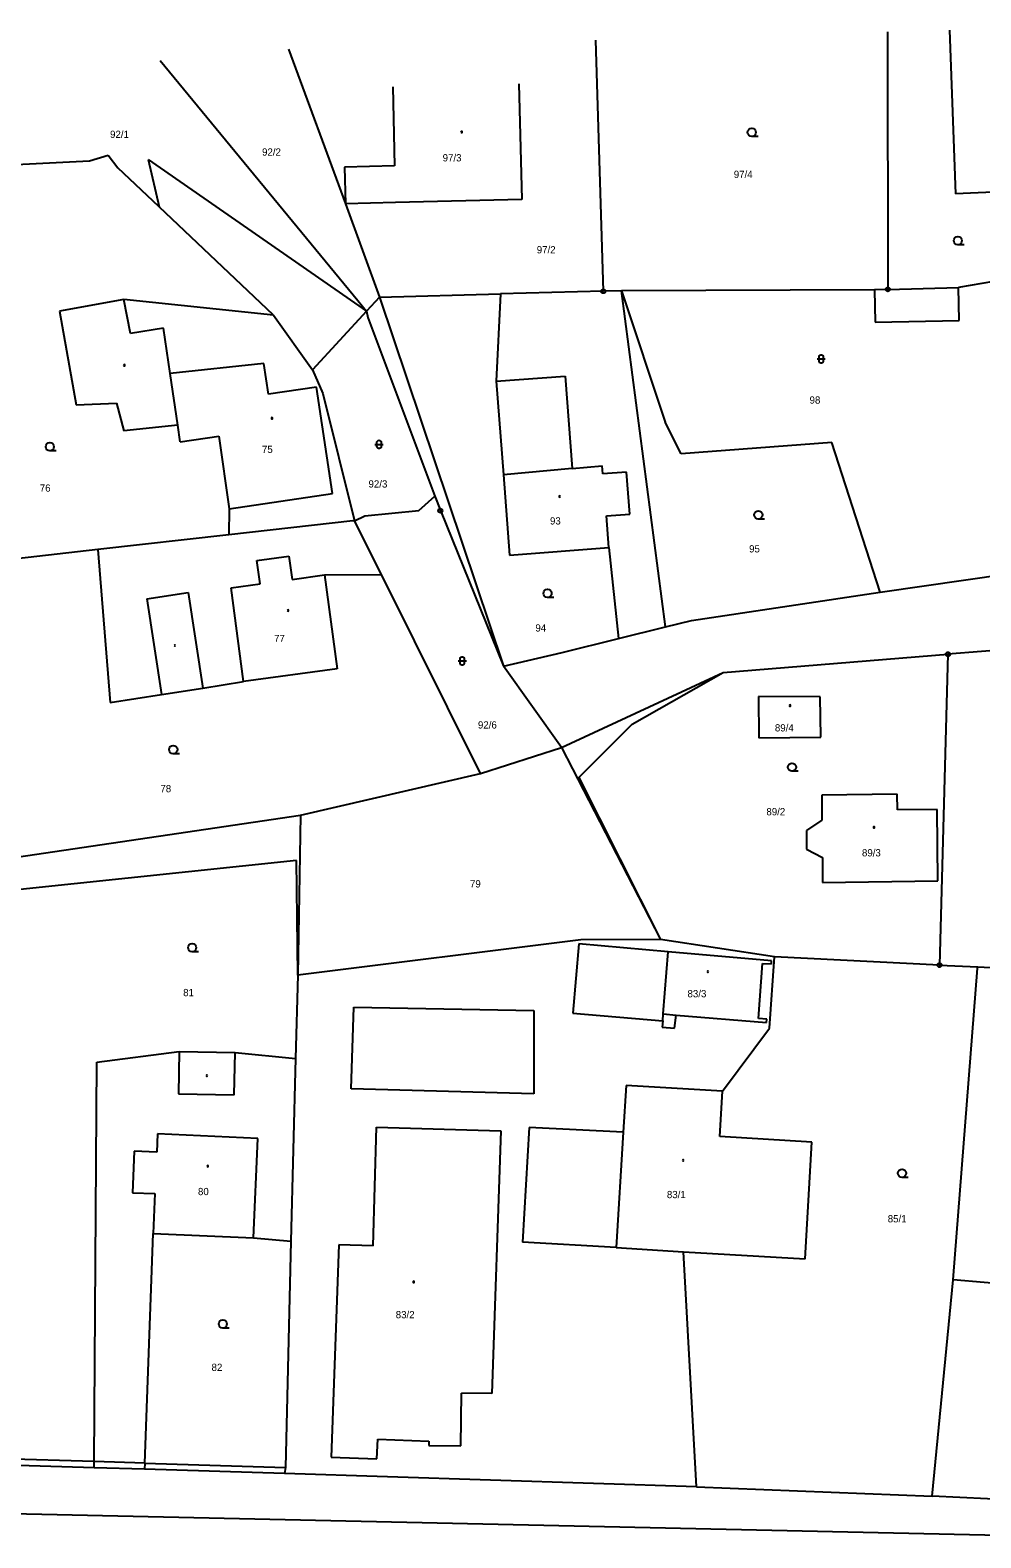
# Model space of a CAD drawing. Extents: x -454285 to -453563, y -1108687 to -1108249.
# Drawn here: x -453773.6 to -453681.8, y -1108476.1 to -1108330.4 of the extents above; entities that cross this region are included whole.
import ezdxf

# ---------------------------------------------------------------- set-up
doc = ezdxf.new("R2010")
doc.units = 0
for name, color, linetype in [('1', 7, 'Continuous'), ('14', 7, 'Continuous'), ('15', 7, 'Continuous'), ('2', 7, 'Continuous'), ('23', 7, 'Continuous'), ('25', 7, 'Continuous'), ('28', 7, 'Continuous')]:
    doc.layers.add(name, color=color, linetype=linetype)

# ---------------------------------------------------------------- blocks, each defined once
blk = doc.blocks.new('Z402')
for start, end in [(0, 180), (180, 0)]:
    blk.add_arc((0, 0), 0.15, start, end)
blk = doc.blocks.new('Z105')
for radius in [0.5, 0.01]:
    blk.add_circle((0, 0), radius)
blk = doc.blocks.new('Z3040')
blk.add_line((1.5, 0), (0, 0))
blk.add_circle((0, 1), 1)
blk = doc.blocks.new('Z3160')
for p, q in [((-1, 1), (1, 1)), ((-0.5, 1.6), (-0.4, 1.8)), ((-0.5, 0.4), (-0.5, 1.6)), ((-0.4, 0.2), (-0.5, 0.4)), ((-0.4, 1.8), (-0.3, 1.9)), ((-0.3, 0.1), (-0.4, 0.2)), ((-0.3, 1.9), (-0.1, 2)), ((-0.1, 0), (-0.3, 0.1)), ((-0.1, 2), (0.1, 2)), ((0.1, 0), (-0.1, 0)), ((0.1, 2), (0.3, 1.9)), ((0.3, 0.1), (0.1, 0)), ((0.3, 1.9), (0.4, 1.8)), ((0.4, 0.2), (0.3, 0.1)), ((0.4, 1.8), (0.5, 1.6)), ((0.5, 0.4), (0.4, 0.2)), ((0.5, 1.6), (0.5, 0.4))]:
    blk.add_line(p, q)

msp = doc.modelspace()

# ---------------------------------------------------------------- linework, layer by layer
at = {"layer": '1'}
for p, q in [((-453719.06, -1108331.41), (-453718.3, -1108355.65)), ((-453690.84, -1108330.6), (-453690.81, -1108355.47)), ((-453684.85, -1108330.43), (-453684.29, -1108346.25)), ((-453748.69, -1108332.26), (-453743.2, -1108347.21)), ((-453761.1, -1108333.35), (-453741.99, -1108356.55)), ((-453738.63, -1108335.9), (-453738.45, -1108343.53)), ((-453726.44, -1108335.6), (-453726.16, -1108346.79)), ((-453784.67, -1108343.91), (-453767.91, -1108343.04)), ((-453767.91, -1108343.04), (-453766.11, -1108342.5)), ((-453766.11, -1108342.5), (-453765.18, -1108343.73)), ((-453762.26, -1108342.93), (-453761.18, -1108347.51)), ((-453762.26, -1108342.93), (-453741.15, -1108357.57)), ((-453761.18, -1108347.51), (-453765.18, -1108343.73)), ((-453738.45, -1108343.53), (-453743.29, -1108343.65)), ((-453743.29, -1108343.65), (-453743.2, -1108347.21)), ((-453679.9, -1108346.05), (-453684.29, -1108346.25)), ((-453750.14, -1108357.95), (-453761.18, -1108347.51)), ((-453738.36, -1108347.09), (-453743.2, -1108347.21)), ((-453743.2, -1108347.21), (-453739.9, -1108356.22)), ((-453726.16, -1108346.79), (-453738.36, -1108347.09)), ((-453679.47, -1108354.5), (-453683.99, -1108355.3)), ((-453739.9, -1108356.22), (-453741.15, -1108357.57)), ((-453739.9, -1108356.22), (-453728.23, -1108355.91)), ((-453728.23, -1108355.91), (-453728.63, -1108364.35)), ((-453718.3, -1108355.65), (-453728.23, -1108355.91)), ((-453716.55, -1108355.6), (-453718.3, -1108355.65)), ((-453692.1, -1108355.5), (-453716.55, -1108355.6)), ((-453712.3, -1108388.07), (-453716.55, -1108355.6)), ((-453716.55, -1108355.6), (-453712.31, -1108368.28)), ((-453690.81, -1108355.47), (-453692.1, -1108355.5)), ((-453690.81, -1108355.47), (-453683.99, -1108355.3)), ((-453764.59, -1108356.45), (-453770.83, -1108357.58)), ((-453770.83, -1108357.58), (-453769.22, -1108366.61)), ((-453750.14, -1108357.95), (-453764.59, -1108356.45)), ((-453741.99, -1108356.55), (-453741.15, -1108357.57)), ((-453741.15, -1108357.57), (-453741.04, -1108358.19)), ((-453750.14, -1108357.95), (-453746.39, -1108363.24)), ((-453741.04, -1108358.19), (-453734.56, -1108375.44)), ((-453746.39, -1108363.24), (-453745.38, -1108365.54)), ((-453728.63, -1108364.35), (-453727.94, -1108373.38)), ((-453769.22, -1108366.61), (-453765.3, -1108366.46)), ((-453765.3, -1108366.46), (-453764.59, -1108369.13)), ((-453745.38, -1108365.54), (-453742.31, -1108377.81)), ((-453759.39, -1108368.58), (-453764.59, -1108369.13)), ((-453759.15, -1108370.2), (-453759.39, -1108368.58)), ((-453710.76, -1108371.35), (-453712.31, -1108368.28)), ((-453759.15, -1108370.2), (-453755.43, -1108369.65)), ((-453755.43, -1108369.65), (-453754.42, -1108376.68)), ((-453696.21, -1108370.26), (-453710.76, -1108371.35)), ((-453691.56, -1108384.72), (-453696.21, -1108370.26)), ((-453727.94, -1108373.38), (-453727.35, -1108381.13)), ((-453754.42, -1108376.68), (-453754.45, -1108379.18)), ((-453734.56, -1108375.44), (-453734.03, -1108376.84)), ((-453742.48, -1108377.83), (-453754.45, -1108379.18)), ((-453742.31, -1108377.81), (-453742.48, -1108377.83)), ((-453739.72, -1108383), (-453742.31, -1108377.81)), ((-453734.03, -1108376.84), (-453727.94, -1108391.86)), ((-453754.45, -1108379.18), (-453767.11, -1108380.61)), ((-453767.11, -1108380.61), (-453779.25, -1108381.98)), ((-453767.11, -1108380.61), (-453765.93, -1108395.36)), ((-453727.35, -1108381.13), (-453717.76, -1108380.4)), ((-453717.76, -1108380.4), (-453716.83, -1108389.19)), ((-453745.21, -1108383.05), (-453739.72, -1108383)), ((-453745.21, -1108383.05), (-453743.99, -1108392.11)), ((-453730.14, -1108402.22), (-453739.72, -1108383)), ((-453691.56, -1108384.72), (-453679.25, -1108382.93)), ((-453709.77, -1108387.45), (-453691.56, -1108384.72)), ((-453716.83, -1108389.19), (-453712.3, -1108388.07)), ((-453712.3, -1108388.07), (-453709.77, -1108387.45)), ((-453722.27, -1108390.53), (-453716.83, -1108389.19)), ((-453671.08, -1108389.58), (-453685.01, -1108390.71)), ((-453727.94, -1108391.86), (-453722.27, -1108390.53)), ((-453706.73, -1108392.47), (-453685.01, -1108390.71)), ((-453685.01, -1108390.71), (-453685.82, -1108420.74)), ((-453743.99, -1108392.11), (-453753.04, -1108393.33)), ((-453722.34, -1108399.73), (-453727.94, -1108391.86)), ((-453722.34, -1108399.73), (-453706.73, -1108392.47)), ((-453760.97, -1108394.6), (-453756.97, -1108393.98)), ((-453756.97, -1108393.98), (-453753.04, -1108393.33)), ((-453765.93, -1108395.36), (-453760.97, -1108394.6)), ((-453703.3, -1108394.8), (-453703.27, -1108398.8)), ((-453697.35, -1108394.81), (-453703.3, -1108394.8)), ((-453697.28, -1108398.72), (-453697.35, -1108394.81)), ((-453730.14, -1108402.22), (-453722.34, -1108399.73)), ((-453722.34, -1108399.73), (-453712.77, -1108418.28)), ((-453703.27, -1108398.8), (-453697.28, -1108398.72)), ((-453747.54, -1108406.26), (-453730.14, -1108402.22)), ((-453689.91, -1108404.23), (-453697.2, -1108404.32)), ((-453697.2, -1108404.32), (-453697.2, -1108406.74)), ((-453689.89, -1108405.74), (-453689.91, -1108404.23)), ((-453686.06, -1108405.72), (-453689.89, -1108405.74)), ((-453685.98, -1108412.61), (-453686.06, -1108405.72)), ((-453774.96, -1108410.31), (-453747.54, -1108406.26)), ((-453747.54, -1108406.26), (-453747.79, -1108421.72)), ((-453697.2, -1108406.74), (-453698.68, -1108407.73)), ((-453698.68, -1108407.73), (-453698.67, -1108409.55)), ((-453698.67, -1108409.55), (-453697.12, -1108410.35)), ((-453697.12, -1108410.35), (-453697.11, -1108412.76)), ((-453697.11, -1108412.76), (-453685.98, -1108412.61)), ((-453720.45, -1108418.31), (-453747.79, -1108421.72)), ((-453720.67, -1108418.7), (-453721.22, -1108425.38)), ((-453712.02, -1108419.45), (-453720.67, -1108418.7)), ((-453712.77, -1108418.28), (-453720.45, -1108418.31)), ((-453701.76, -1108419.94), (-453712.77, -1108418.28)), ((-453702.04, -1108420.32), (-453712.02, -1108419.45)), ((-453702.25, -1108426.83), (-453701.76, -1108419.94)), ((-453702.06, -1108420.63), (-453702.04, -1108420.32)), ((-453685.82, -1108420.74), (-453701.76, -1108419.94)), ((-453747.79, -1108421.72), (-453748.01, -1108429.76)), ((-453703.31, -1108425.9), (-453702.93, -1108420.57)), ((-453702.93, -1108420.57), (-453702.06, -1108420.63)), ((-453685.82, -1108420.74), (-453682.13, -1108420.92)), ((-453684.51, -1108451.15), (-453682.14, -1108421.04)), ((-453682.14, -1108421.04), (-453682.13, -1108420.92)), ((-453682.13, -1108420.92), (-453675.26, -1108421.26)), ((-453721.22, -1108425.38), (-453712.55, -1108426.11)), ((-453712.55, -1108426.11), (-453712.6, -1108426.74)), ((-453711.42, -1108426.84), (-453711.26, -1108425.58)), ((-453711.26, -1108425.58), (-453702.53, -1108426.29)), ((-453702.51, -1108425.96), (-453703.31, -1108425.9)), ((-453702.53, -1108426.29), (-453702.51, -1108425.96)), ((-453712.6, -1108426.74), (-453711.42, -1108426.84)), ((-453706.79, -1108432.92), (-453702.25, -1108426.83)), ((-453767.2, -1108430.1), (-453759.25, -1108429.07)), ((-453759.25, -1108429.07), (-453753.85, -1108429.18)), ((-453753.85, -1108429.18), (-453748.01, -1108429.76)), ((-453767.46, -1108468.7), (-453767.2, -1108430.1)), ((-453748.01, -1108429.76), (-453748.48, -1108447.4)), ((-453707.05, -1108437.31), (-453706.79, -1108432.92)), ((-453740.53, -1108447.87), (-453740.19, -1108436.38)), ((-453740.19, -1108436.38), (-453728.19, -1108436.76)), ((-453728.19, -1108436.76), (-453729.07, -1108462.13)), ((-453698.14, -1108437.84), (-453707.05, -1108437.31)), ((-453698.81, -1108449.12), (-453698.14, -1108437.84)), ((-453762.58, -1108468.85), (-453761.77, -1108446.66)), ((-453761.77, -1108446.66), (-453752.08, -1108447.09)), ((-453752.08, -1108447.09), (-453748.48, -1108447.4)), ((-453748.48, -1108447.4), (-453749, -1108469.26)), ((-453743.85, -1108447.75), (-453744.58, -1108468.26)), ((-453740.53, -1108447.87), (-453743.85, -1108447.75)), ((-453709.29, -1108471.14), (-453710.56, -1108448.42)), ((-453710.56, -1108448.42), (-453698.81, -1108449.12)), ((-453686.52, -1108472.05), (-453684.51, -1108451.15)), ((-453677.48, -1108451.74), (-453684.51, -1108451.15)), ((-453732.04, -1108467.18), (-453731.98, -1108462.09)), ((-453729.07, -1108462.13), (-453731.98, -1108462.09)), ((-453740.15, -1108468.43), (-453740.07, -1108466.52)), ((-453740.07, -1108466.52), (-453735.14, -1108466.71)), ((-453735.14, -1108466.71), (-453735.15, -1108467.14)), ((-453744.58, -1108468.26), (-453740.15, -1108468.43)), ((-453735.15, -1108467.14), (-453732.04, -1108467.18)), ((-453767.46, -1108469.29), (-453776.89, -1108469)), ((-453767.46, -1108469.29), (-453767.46, -1108468.7)), ((-453762.6, -1108469.44), (-453767.46, -1108469.29)), ((-453762.58, -1108468.85), (-453762.6, -1108469.44)), ((-453749.08, -1108469.86), (-453762.6, -1108469.44)), ((-453749, -1108469.26), (-453749.08, -1108469.86)), ((-453709.29, -1108471.14), (-453749.08, -1108469.86)), ((-453709.29, -1108471.14), (-453686.52, -1108472.05)), ((-453667.9, -1108472.91), (-453686.52, -1108472.05))]:
    msp.add_line(p, q, dxfattribs=at)
msp.add_lwpolyline([(-453742.31, -1108377.81), (-453741.34, -1108377.35), (-453736.1, -1108376.82), (-453734.56, -1108375.44)], dxfattribs=at)
at = {"layer": '2'}
for p, q in [((-453739.9, -1108356.22), (-453727.94, -1108391.86)), ((-453692.1, -1108355.5), (-453692.04, -1108358.63)), ((-453683.93, -1108358.47), (-453683.99, -1108355.3)), ((-453763.96, -1108359.72), (-453764.59, -1108356.45)), ((-453741.15, -1108357.57), (-453746.39, -1108363.24)), ((-453760.76, -1108359.22), (-453763.96, -1108359.72)), ((-453760.12, -1108363.61), (-453760.76, -1108359.22)), ((-453692.04, -1108358.63), (-453683.93, -1108358.47)), ((-453751.08, -1108362.63), (-453760.12, -1108363.61)), ((-453759.39, -1108368.58), (-453760.12, -1108363.61)), ((-453750.64, -1108365.59), (-453751.08, -1108362.63)), ((-453745.98, -1108364.9), (-453750.64, -1108365.59)), ((-453744.46, -1108375.2), (-453745.98, -1108364.9)), ((-453728.63, -1108364.35), (-453721.97, -1108363.84)), ((-453721.97, -1108363.84), (-453721.29, -1108372.78)), ((-453721.29, -1108372.78), (-453727.94, -1108373.38)), ((-453721.29, -1108372.78), (-453718.4, -1108372.51)), ((-453718.34, -1108373.29), (-453718.4, -1108372.51)), ((-453716.05, -1108373.12), (-453718.34, -1108373.29)), ((-453715.74, -1108377.18), (-453716.05, -1108373.12)), ((-453754.42, -1108376.68), (-453744.46, -1108375.2)), ((-453717.99, -1108377.35), (-453715.74, -1108377.18)), ((-453717.76, -1108380.4), (-453717.99, -1108377.35)), ((-453751.74, -1108381.66), (-453748.65, -1108381.24)), ((-453751.44, -1108383.91), (-453751.74, -1108381.66)), ((-453748.65, -1108381.24), (-453748.35, -1108383.49)), ((-453754.25, -1108384.29), (-453751.44, -1108383.91)), ((-453748.35, -1108383.49), (-453745.21, -1108383.05)), ((-453762.39, -1108385.35), (-453758.39, -1108384.74)), ((-453762.39, -1108385.35), (-453760.97, -1108394.6)), ((-453758.39, -1108384.74), (-453756.97, -1108393.98)), ((-453753.04, -1108393.33), (-453754.25, -1108384.29)), ((-453715.52, -1108397.47), (-453706.73, -1108392.47)), ((-453720.64, -1108402.63), (-453715.52, -1108397.47)), ((-453720.64, -1108402.63), (-453712.77, -1108418.28)), ((-453747.94, -1108410.65), (-453774.63, -1108413.45)), ((-453747.79, -1108421.72), (-453747.94, -1108410.65)), ((-453712.5, -1108425.46), (-453712.02, -1108419.45)), ((-453742.64, -1108432.68), (-453742.4, -1108424.8)), ((-453742.4, -1108424.8), (-453724.99, -1108425.12)), ((-453724.99, -1108425.12), (-453725, -1108433.16)), ((-453712.55, -1108426.11), (-453712.5, -1108425.46)), ((-453712.5, -1108425.46), (-453711.26, -1108425.58)), ((-453759.25, -1108429.07), (-453759.33, -1108433.17)), ((-453753.93, -1108433.28), (-453753.85, -1108429.18)), ((-453759.33, -1108433.17), (-453753.93, -1108433.28)), ((-453725, -1108433.16), (-453742.64, -1108432.68)), ((-453716.1, -1108432.36), (-453716.37, -1108436.88)), ((-453706.79, -1108432.92), (-453716.1, -1108432.36)), ((-453725.45, -1108436.41), (-453726.11, -1108447.49)), ((-453716.37, -1108436.88), (-453725.45, -1108436.41)), ((-453761.34, -1108437.05), (-453761.42, -1108438.82)), ((-453751.65, -1108437.48), (-453761.34, -1108437.05)), ((-453752.08, -1108447.09), (-453751.65, -1108437.48)), ((-453716.37, -1108436.88), (-453717.04, -1108448.03)), ((-453763.59, -1108438.72), (-453763.78, -1108442.72)), ((-453761.42, -1108438.82), (-453763.59, -1108438.72)), ((-453763.78, -1108442.72), (-453761.6, -1108442.81)), ((-453761.6, -1108442.81), (-453761.77, -1108446.66)), ((-453717.04, -1108448.03), (-453726.11, -1108447.49)), ((-453717.04, -1108448.03), (-453710.56, -1108448.42)), ((-453767.46, -1108468.7), (-453776.37, -1108468.43)), ((-453762.58, -1108468.85), (-453767.46, -1108468.7)), ((-453762.58, -1108468.85), (-453749, -1108469.26)), ((-453670.23, -1108476.06), (-453858.46, -1108471.89))]:
    msp.add_line(p, q, dxfattribs=at)

# ---------------------------------------------------------------- block references
at = {"layer": '23', "xscale": 0.4, "yscale": 0.4000000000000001}
for name, p in [('Z3040', (-453703.95, -1108340.7)), ('Z3040', (-453684.05, -1108351.16)), ('Z3160', (-453697.25, -1108362.59)), ('Z3040', (-453771.75, -1108371.07)), ('Z3160', (-453739.95, -1108370.85)), ('Z3040', (-453703.32, -1108377.65)), ('Z3040', (-453723.68, -1108385.23)), ('Z3160', (-453731.92, -1108391.76)), ('Z3040', (-453759.83, -1108400.32)), ('Z3040', (-453700.07, -1108402.02)), ('Z3040', (-453758, -1108419.45)), ('Z3040', (-453689.44, -1108441.24)), ('Z3040', (-453755.04, -1108455.8))]:
    msp.add_blockref(name, p, dxfattribs=at)
at = {"layer": '25', "xscale": 0.4, "yscale": 0.4000000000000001}
for p in [(-453731.98, -1108340.27), (-453764.56, -1108362.8), (-453750.29, -1108367.92), (-453722.5, -1108375.47), (-453748.75, -1108386.49), (-453759.67, -1108389.87), (-453700.27, -1108395.67), (-453692.15, -1108407.43), (-453708.2, -1108421.37), (-453756.59, -1108431.41), (-453756.51, -1108440.16), (-453710.58, -1108439.6), (-453736.61, -1108451.34)]:
    msp.add_blockref('Z402', p, dxfattribs=at)
at = {"layer": '28', "xscale": 0.4, "yscale": 0.4000000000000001}
for p in [(-453718.3, -1108355.65), (-453690.81, -1108355.47), (-453734.03, -1108376.84), (-453685.01, -1108390.71), (-453685.82, -1108420.74)]:
    msp.add_blockref('Z105', p, dxfattribs=at)

# ---------------------------------------------------------------- texts
at = {"layer": '14'}
for s, p in [('92/1', (-453765.93, -1108340.84)), ('92/2', (-453751.25, -1108342.55)), ('97/4', (-453705.69, -1108344.71)), ('97/2', (-453724.72, -1108351.99)), ('98', (-453698.37, -1108366.51)), ('92/3', (-453740.97, -1108374.61)), ('76', (-453772.72, -1108375.01)), ('95', (-453704.21, -1108380.88)), ('94', (-453724.85, -1108388.52)), ('92/6', (-453730.4, -1108397.89)), ('78', (-453761.07, -1108404.04)), ('89/2', (-453702.54, -1108406.27)), ('79', (-453731.17, -1108413.24)), ('81', (-453758.87, -1108423.74)), ('85/1', (-453690.82, -1108445.59)), ('82', (-453756.13, -1108459.94))]:
    msp.add_text(s, height=0.7, dxfattribs=at).set_placement(p)
at = {"layer": '15'}
for s, p in [('97/3', (-453733.81, -1108343.11)), ('75', (-453751.26, -1108371.27)), ('93', (-453723.44, -1108378.18)), ('77', (-453750.09, -1108389.54)), ('89/4', (-453701.72, -1108398.17)), ('89/3', (-453693.31, -1108410.24)), ('83/3', (-453710.16, -1108423.85)), ('80', (-453757.44, -1108442.96)), ('83/1', (-453712.15, -1108443.25)), ('83/2', (-453738.34, -1108454.85))]:
    msp.add_text(s, height=0.7, dxfattribs=at).set_placement(p)

doc.saveas('drawing.dxf')
